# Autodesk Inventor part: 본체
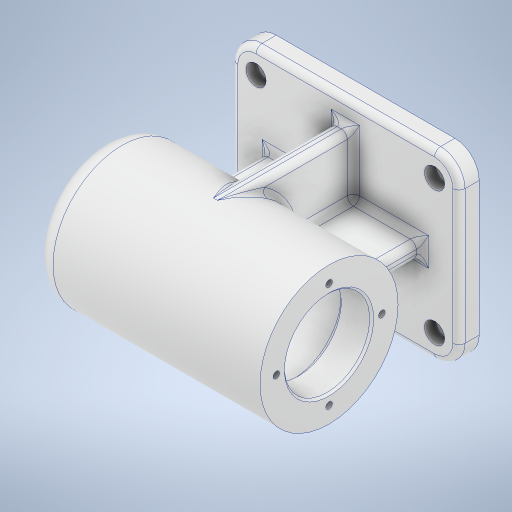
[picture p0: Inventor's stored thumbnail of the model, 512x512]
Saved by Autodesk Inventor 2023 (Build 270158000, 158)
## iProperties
Created: 2026-08
Part Number: 본체
Material: 알루미늄 6061
Document SubType Name: Modeling
Designer: home
Density: 2.7 g/cm^3
Appearance: 알루미늄 - 평지
Mass: 1026.01 g
Surface Area: 757.776 cm^2
Volume: 380.003 cm^3
Author: home
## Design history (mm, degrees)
sketch "스케치1"
  geometry: L1 (0, 0)-(-126.294, 0); L2 (-112, 0)-(-112, 24); L3 (-102, 34)-(0, 34); L4 (0, 34)-(0, 0); L5 (0, 21)-(-15, 21); L6 (-15, 21)-(-15, 24); L7 (-15, 24)-(-69, 24); L8 (-69, 24)-(-69, 21); L9 (-69, 21)-(-81, 21); L10 (-81, 21)-(-81, 17.5); L11 (-81, 17.5)-(-99, 17.5); L12 (-99, 17.5)-(-99, 16); L13 (-99, 16)-(-103, 16); L14 (-103, 16)-(-103, 10.5); L15 (-103, 10.5)-(-106, 10.5); L16 (-106, 10.5)-(-106, 0); A1 r 10 centre (-102, 24) between (-102, 34) and (-112, 24); 1 further point
  constraints: 32 end point, 13 perpendicular, 7 point on line, 2 point on circle, 2 tangent, 1 centre point, 1 horizontal, 1 vertical
  dimensions: "d0" = 68 diameter of L3 L1; "d1" = 112 distance of point (-112, 34) L3.end; "d2" = 42 diameter of L5 L1; "d3" = 48 diameter of L7 L1; "d4" = 35 diameter of L11 L1; "d5" = 32 diameter of L13 L1; "d6" = 21 diameter of L15 L1; "d7" = 15 distance of L5.start L5.end; "d8" = 54 distance of L6.end L7.end; "d9" = 81 distance between parallel lines of L4 L10; "d10" = 18 distance of L10.end L11.end; "d11" = 103 distance between parallel lines of L4 L14; "d12" = 3 distance of L14.end L15.end; "d13" = 10 radius of A1
revolve "회전1" sketch "스케치1" stored, may be unused: angle "d14" = 90 deg
node "작업 평면2"
sketch "스케치3"
  geometry: L1 (-112, 45)-(0, 45); L2 (0, 45)-(0, -45); L3 (0, -45)-(-112, -45); L4 (-112, -45)-(-112, 45); 2 further points
  constraints: 8 end point, 2 parallel, 1 coincident, 1 horizontal, 1 midpoint, 1 perpendicular
  dimensions: "d17" = 112 distance of L2.end L3.end; "d18" = 90 distance of L1.end L2.end
extrude "돌출1" join sketch "스케치3" distance "d19" = 10; taper "d20" = 0 deg
fillet "모깎기1" dims "d21" = 12
sketch "스케치4"
  geometry: L1 (-112, 33)-(-112, -33) reference; L2 (-12, 45)-(-100, 45) reference; L3 (0, -33)-(0, 33) reference; L4 (-100, -45)-(-12, -45) reference; 5 further points
  constraints: 2 horizontal alignment, 2 vertical alignment
  dimensions: "d29" = 12 distance from line of point (-100, 33) L1; "d30" = 12 distance from line of L2 point (-100, 33); "d31" = 12 distance from line of L3 point (-12, 33); "d32" = 12 distance from line of L4 point (-100, -33)
hole "구멍1" sketch "스케치4" at (-100, 33), (-12, 33), (-12, -33), (-100, -33) diameter "d22" = 5.5; stored, may be unused: countersink angle "d26" = 90 deg, drill point angle "d28" = 118 deg; dims "d23" = 6, "d24" = 10, "d25" = 5.5, "d27" = 8
sketch "스케치5"
  geometry: L1 (-94, 4)-(-18, 4); L2 (-18, 4)-(-18, -4); L3 (-18, -4)-(-94, -4); L4 (-94, -4)-(-94, 4); L5 (-100, -45)-(-12, -45) reference; 4 further points
  constraints: 8 end point, 3 midpoint, 2 parallel, 1 horizontal, 1 horizontal alignment, 1 perpendicular, 1 vertical alignment
  dimensions: "d33" = 8 distance of L1.end L2.end; "d34" = 76 distance of L1.start L1.end
extrude "돌출2" join sketch "스케치5" stored distance "d35" = 10; taper "d36" = 0 deg
node "작업 평면3"
sketch "스케치6"
  geometry: L1 (-74, -1)-(-10, -1); L2 (-10, 66)-(-10, 0) reference; L3 (-10, 33)-(-10, -1); L4 (-10, 29)-(-40.236, 29) reference; L5 (-40.236, 29)-(-10, 29); A1 r 34 centre (-74, 33) between (-74, -1) and (-40.236, 29) reference; 3 further points
  constraints: 6 end point, 1 coincident, 1 collinear, 1 horizontal, 1 midpoint, 1 point on circle, 1 point on line, 1 vertical, 1 vertical alignment, 2 other
  dimensions: "d38" = 34 distance from line of L3.start L1
extrude "돌출3" join sketch "스케치6" stored distance "d39" = 8; taper "d40" = 0 deg
sketch "스케치7" dims "d41" = 52
  geometry: L1 (0, 0)-(-26, 0); L2 (-26, 0)-(0, 0); 2 further points
  constraints: 4 end point, 2 coincident, 2 horizontal, 1 horizontal alignment, 2 other
hole "구멍2" sketch "스케치7" at (-26, 0) diameter "d42" = 3.242; stored, may be unused: countersink angle "d46" = 90 deg, drill point angle "d48" = 118 deg; dims "d43" = 8, "d44" = 10, "d45" = 5.5, "d47" = 10
sketch "스케치8"
  geometry: L1 (21.951, 6)-(66.049, 6); L2 (66.049, 6)-(66.049, 0); L3 (66.049, 0)-(21.951, 0); L4 (21.951, 0)-(21.951, 6); L5 (0, 0)-(88, 0) reference; L6 (0, 10)-(88, 10) reference; 4 further points
  constraints: 3 midpoint, 1 horizontal, 1 point on line, 1 vertical alignment, 2 other
  dimensions: "d52" = 3 distance from line of L5 point (66.049, 3)
feature "엠보싱1" sketch "스케치8" dims "d0" = 68, "d1" = 112, "d2" = 42, "d3" = 48, "d4" = 35, "d5" = 32, "d6" = 21, "d7" = 15, "d8" = 54, "d9" = 81, "d10" = 18, "d11" = 103, "d12" = 3, "d13" = 10, "d16" = -74, "d53" = 0.5, "d54" = 0
fillet "모깎기2" dims "d55" = 3
fillet "모깎기3" dims "d56" = 3
fillet "모깎기4" dims "d57" = 3
fillet "모깎기5" dims "d58" = 3
chamfer "모따기1" distance "d59" = 1; stored, may be unused: second distance "d60" = 2, angle "d61" = 45 deg
fillet "모깎기6" dims "d62" = 0.6
fillet "모깎기7" dims "d63" = 3
fillet "모깎기8" dims "d64" = 3
feature "˺耀˼耀˾耀̀耀̂耀̄耀̆耀̈耀" dims "d0" = 68, "d1" = 112, "d2" = 42, "d3" = 48, "d4" = 35, "d5" = 32, "d6" = 21, "d7" = 15, "d8" = 54, "d9" = 81, "d10" = 18, "d11" = 103, "d12" = 3, "d13" = 10, "d14" = 90 deg, "d16" = -74, "d17" = 112, "d18" = 90, "d19" = 10, "d20" = 0, "d21" = 12, "d22" = 5.5, "d23" = 6, "d24" = 10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
node "솔리드1"
mirror "미러1"
pattern_circular "원형 패턴1" dims angle "d50" = 360 deg
feature "A9D066F2-1C7D-4E18-AEED-F7BC21143FA4" dims "d42" = 3.242, "d43" = 8, "d44" = 10, "d45" = 5.5, "d46" = 90 deg, "d47" = 10, "d48" = 118 deg
